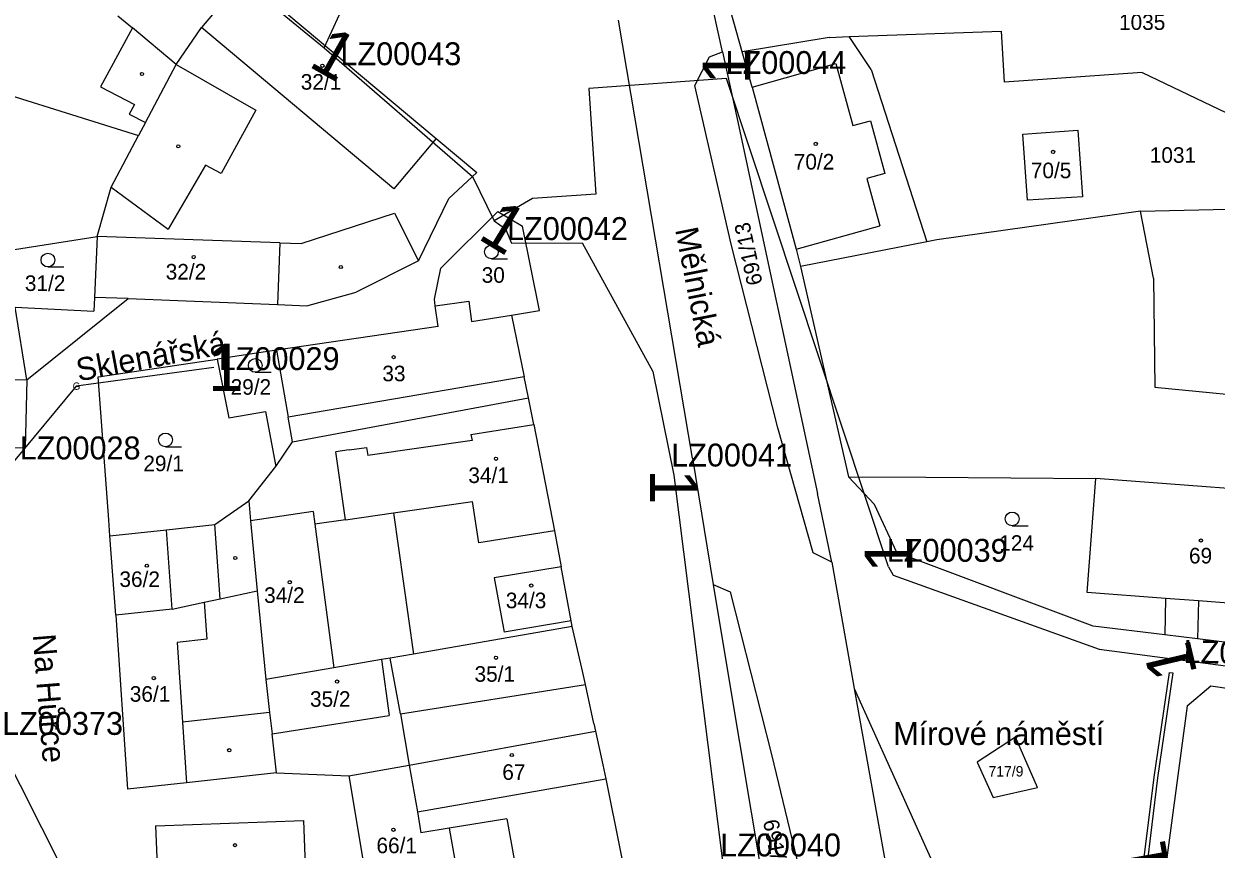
# Model space of a CAD drawing. Extents: x -738131 to -734179, y -1033447 to -1030078.
# Drawn here: x -736178.6 to -736048.4, y -1032166.9 to -1032076.8 of the extents above; entities that cross this region are included whole.
import ezdxf

# ---------------------------------------------------------------- set-up
doc = ezdxf.new("R2010")
doc.units = 0
for name, color, linetype in [('ftf_2010', 7, 'Continuous'), ('ftf_2050', 7, 'Continuous'), ('ftf_2080', 7, 'Continuous'), ('ftf_2140', 7, 'Continuous'), ('ftf_3010', 7, 'Continuous'), ('ftf_3010_ftf_3010_gtda_3015_gtda_3015_1', 7, 'Continuous'), ('ftf_3240', 7, 'Continuous'), ('ftf_nu', 7, 'Continuous'), ('Vrstva 1', 7, 'Continuous'), ('Vrstva 2', 7, 'Continuous'), ('Vrstva 3', 7, 'Continuous'), ('Vrstva 4', 7, 'Continuous'), ('Vrstva 5', 7, 'Continuous')]:
    doc.layers.add(name, color=color, linetype=linetype)

msp = doc.modelspace()

# ---------------------------------------------------------------- linework, layer by layer
at = {"layer": 'ftf_2010'}
for points in [[(-736173.87, -1032059), (-736155.52, -1032071.43), (-736145.76, -1032079.46)], [(-736145.76, -1032079.46), (-736129.57, -1032093.5), (-736127.21, -1032098.34)], [(-736101.83, -1032082.79), (-736116.85, -1032083.87), (-736116.08, -1032095.41), (-736123, -1032095.88), (-736127.21, -1032098.34)], [(-736084.14, -1032136.1), (-736101.83, -1032082.79)], [(-736127.21, -1032098.34), (-736125.97, -1032099.2), (-736125.31, -1032100.78), (-736117.57, -1032100.74), (-736109.87, -1032114.77), (-736107.59, -1032126.1)], [(-736107.59, -1032126.1), (-736102.25, -1032168.26)], [(-736084.14, -1032136.1), (-736083.63, -1032137.03), (-736061.14, -1032145.09), (-736042.04, -1032147.61), (-736033.38, -1032147.59)], [(-736053.07, -1032147.7), (-736054.74, -1032159.15), (-736056, -1032169.35)]]:
    msp.add_lwpolyline(points, dxfattribs=at)
at = {"layer": 'ftf_2050'}
for points in [[(-736157.8, -1032114.33), (-736172.83, -1032116.38), (-736179.72, -1032124.69)], [(-736181.33, -1032155.34), (-736169.66, -1032178.44)]]:
    msp.add_lwpolyline(points, dxfattribs=at)
at = {"layer": 'ftf_2080'}
msp.add_lwpolyline([(-736145.76, -1032079.46), (-736141.56, -1032070.31)], dxfattribs=at)
at = {"layer": 'ftf_2140'}
msp.add_lwpolyline([(-736059.51, -1032203.25), (-736059.59, -1032203.64), (-736061.73, -1032203.22), (-736058.65, -1032185.85), (-736058.24, -1032185.72), (-736058.61, -1032185.64), (-736057.52, -1032177.44), (-736056.42, -1032169.43), (-736056, -1032169.35), (-736056.4, -1032169.3), (-736055.13, -1032159.09), (-736053.46, -1032147.65), (-736053.07, -1032147.7)], dxfattribs=at)
at = {"layer": 'Vrstva 1'}
for points in [[(-736154.53, -1032071.72), (-736159.15, -1032077.23)], [(-736154.53, -1032071.72), (-736133.52, -1032089.34)], [(-736102.26, -1032079.87), (-736103.75, -1032073.06)], [(-736100.1, -1032079.88), (-736101.68, -1032074.32)], [(-736105.53, -1032124.24), (-736113.62, -1032076.42)], [(-736161.91, -1032081.28), (-736159.15, -1032077.23)], [(-736088.44, -1032078.22), (-736071.79, -1032077.63)], [(-736071.46, -1032083.19), (-736071.79, -1032077.63)], [(-736090.61, -1032078.3), (-736100.1, -1032079.88)], [(-736090.61, -1032078.3), (-736088.44, -1032078.22)], [(-736086.02, -1032081.8), (-736088.44, -1032078.22)], [(-736103.68, -1032080.44), (-736102.26, -1032079.87)], [(-736102.26, -1032079.87), (-736100.66, -1032087.2)], [(-736099.01, -1032083.73), (-736100.1, -1032079.88)], [(-736165.28, -1032087.61), (-736161.91, -1032081.28)], [(-736105.27, -1032083.57), (-736103.68, -1032080.44)], [(-736187.43, -1032082.32), (-736166.03, -1032089.02)], [(-736086.02, -1032081.8), (-736079.93, -1032100.61)], [(-736056.43, -1032082.12), (-736071.46, -1032083.19)], [(-736056.43, -1032082.12), (-736039.76, -1032090.12)], [(-736101.33, -1032100.88), (-736105.27, -1032083.57)], [(-736099.01, -1032083.73), (-736094.2, -1032101.44)], [(-736165.28, -1032087.61), (-736166.03, -1032089.02)], [(-736100.66, -1032087.2), (-736091.9, -1032128.1)], [(-736169.02, -1032094.66), (-736166.03, -1032089.02)], [(-736133.52, -1032089.34), (-736129.08, -1032093.07)], [(-736069.48, -1032088.87), (-736063.45, -1032088.43)], [(-736068.97, -1032096.09), (-736069.48, -1032088.87)], [(-736063.45, -1032088.43), (-736062.95, -1032095.7)], [(-736129.08, -1032093.07), (-736132.15, -1032095.9)], [(-736170.56, -1032100.05), (-736169.02, -1032094.66)], [(-736135.47, -1032102.71), (-736132.15, -1032095.9)], [(-736062.95, -1032095.7), (-736068.97, -1032096.09)], [(-736056.61, -1032097.28), (-736039.13, -1032096.86)], [(-736133.01, -1032103.51), (-736126.81, -1032097.31)], [(-736126.81, -1032097.31), (-736124.12, -1032098.92)], [(-736056.61, -1032097.28), (-736078.84, -1032100.39)], [(-736055.2, -1032104.58), (-736056.61, -1032097.28)], [(-736122.26, -1032108.13), (-736124.12, -1032098.92)], [(-736181.49, -1032101.76), (-736170.56, -1032100.05)], [(-736170.56, -1032100.05), (-736170.85, -1032106.69)], [(-736150.62, -1032100.73), (-736170.56, -1032100.05)], [(-736150.62, -1032100.73), (-736150.85, -1032107.48)], [(-736096.21, -1032120.92), (-736101.33, -1032100.88)], [(-736079.93, -1032100.61), (-736093.76, -1032103.33)], [(-736078.84, -1032100.39), (-736079.93, -1032100.61)], [(-736094.2, -1032101.44), (-736093.76, -1032103.33)], [(-736135.47, -1032102.71), (-736142.26, -1032106.12)], [(-736133.73, -1032106.9), (-736133.01, -1032103.51)], [(-736093.76, -1032103.33), (-736088.49, -1032126.28)], [(-736055.2, -1032104.58), (-736055.04, -1032116.5)], [(-736147.66, -1032107.6), (-736142.26, -1032106.12)], [(-736178.24, -1032115.68), (-736167.17, -1032106.83)], [(-736170.85, -1032106.69), (-736170.91, -1032108.19)], [(-736167.17, -1032106.83), (-736150.85, -1032107.48)], [(-736150.85, -1032107.48), (-736147.66, -1032107.6)], [(-736133.63, -1032107.61), (-736133.73, -1032106.9)], [(-736133.63, -1032107.61), (-736129.97, -1032107.1)], [(-736133.32, -1032109.86), (-736133.63, -1032107.61)], [(-736129.97, -1032107.1), (-736129.66, -1032109.32)], [(-736178.24, -1032115.68), (-736179.52, -1032107.77)], [(-736179.52, -1032107.77), (-736170.91, -1032108.19)], [(-736129.66, -1032109.32), (-736125.32, -1032108.62)], [(-736125.32, -1032108.62), (-736122.26, -1032108.13)], [(-736125.32, -1032108.62), (-736123.92, -1032115.35)], [(-736133.32, -1032109.86), (-736150.98, -1032112.47)], [(-736150.98, -1032112.47), (-736157.46, -1032113.43)], [(-736150.98, -1032112.47), (-736149.68, -1032119.76)], [(-736170.43, -1032115.35), (-736157.46, -1032113.43)], [(-736157.46, -1032113.43), (-736156.18, -1032119.86)], [(-736169.29, -1032130.98), (-736170.43, -1032115.35)], [(-736123.46, -1032117.67), (-736123.92, -1032115.35)], [(-736191.64, -1032115.51), (-736178.24, -1032115.68)], [(-736178.24, -1032115.68), (-736178.43, -1032123.14)], [(-736055.04, -1032116.5), (-736026.73, -1032119.25)], [(-736149.21, -1032122.45), (-736123.46, -1032117.67)], [(-736122.88, -1032120.58), (-736123.46, -1032117.67)], [(-736156.18, -1032119.86), (-736152.18, -1032119.16)], [(-736152.18, -1032119.16), (-736151.03, -1032125.16)], [(-736149.21, -1032122.45), (-736149.68, -1032119.76)], [(-736122.88, -1032120.58), (-736120.62, -1032132.18)], [(-736092.35, -1032134.6), (-736096.21, -1032120.92)], [(-736178.43, -1032123.14), (-736180.63, -1032123.11)], [(-736151.03, -1032125.16), (-736149.21, -1032122.45)], [(-736105.53, -1032124.24), (-736103.27, -1032138.05)], [(-736154, -1032128.89), (-736151.03, -1032125.16)], [(-736085.67, -1032129.29), (-736088.49, -1032126.28)], [(-736088.49, -1032126.28), (-736080.05, -1032126.33)], [(-736080.05, -1032126.33), (-736061.48, -1032126.45)], [(-736062.43, -1032138.91), (-736061.48, -1032126.45)], [(-736090.33, -1032135.6), (-736091.9, -1032128.1)], [(-736157.72, -1032131.5), (-736154, -1032128.89)], [(-736154, -1032128.89), (-736153.79, -1032131.08)], [(-736138.2, -1032130.23), (-736129.55, -1032128.99)], [(-736128.87, -1032133.49), (-736129.55, -1032128.99)], [(-736083.23, -1032134.54), (-736085.67, -1032129.29)], [(-736169.16, -1032132.74), (-736169.29, -1032130.98)], [(-736146.95, -1032130.06), (-736153.79, -1032131.08)], [(-736153.79, -1032131.08), (-736153.07, -1032138.72)], [(-736146.95, -1032130.06), (-736146.77, -1032131.45)], [(-736143.45, -1032130.98), (-736146.77, -1032131.45)], [(-736143.45, -1032130.98), (-736138.2, -1032130.23)], [(-736138.2, -1032130.23), (-736136.02, -1032145.63)], [(-736169.16, -1032132.74), (-736162.98, -1032132.07)], [(-736162.98, -1032132.07), (-736157.72, -1032131.5)], [(-736120.62, -1032132.18), (-736128.87, -1032133.49)], [(-736120.62, -1032132.18), (-736119.89, -1032136.11)], [(-736168.53, -1032141.4), (-736169.16, -1032132.74)], [(-736090.33, -1032135.6), (-736092.35, -1032134.6)], [(-736061.77, -1032142.59), (-736083.23, -1032134.54)], [(-736118.8, -1032142.01), (-736119.89, -1032136.11)], [(-736090.33, -1032135.6), (-736087.87, -1032149.39)], [(-736157.13, -1032139.6), (-736153.07, -1032138.72)], [(-736153.07, -1032138.72), (-736152.14, -1032148.42)], [(-736103.27, -1032138.05), (-736101.43, -1032138.83)], [(-736103.27, -1032138.05), (-736101.65, -1032147.92)], [(-736101.43, -1032138.83), (-736096.91, -1032156.59)], [(-736053.87, -1032139.56), (-736062.43, -1032138.91)], [(-736162.35, -1032140.73), (-736158.86, -1032139.97)], [(-736158.86, -1032139.97), (-736157.13, -1032139.6)], [(-736053.87, -1032139.56), (-736053.96, -1032143.54)], [(-736050.28, -1032139.83), (-736050.38, -1032143.98)], [(-736041.89, -1032140.47), (-736050.28, -1032139.83)], [(-736162.35, -1032140.73), (-736168.53, -1032141.4)], [(-736168.53, -1032141.4), (-736167.25, -1032160.38)], [(-736118.69, -1032142.63), (-736136.02, -1032145.63)], [(-736118.69, -1032142.63), (-736118.8, -1032142.01)], [(-736117.51, -1032147.64), (-736118.69, -1032142.63)], [(-736053.96, -1032143.54), (-736061.77, -1032142.59)], [(-736050.38, -1032143.98), (-736053.96, -1032143.54)], [(-736041.81, -1032145.03), (-736050.38, -1032143.98)], [(-736139.51, -1032146.24), (-736144.71, -1032147.13)], [(-736138.55, -1032146.07), (-736139.51, -1032146.24)], [(-736136.02, -1032145.63), (-736138.55, -1032146.07)], [(-736137.44, -1032152.17), (-736138.55, -1032146.07)], [(-736144.71, -1032147.13), (-736152.14, -1032148.42)], [(-736117.23, -1032148.95), (-736117.51, -1032147.64)], [(-736101.65, -1032147.92), (-736095.37, -1032185.27)], [(-736152.14, -1032148.42), (-736151.72, -1032152.03)], [(-736116.32, -1032153.2), (-736117.23, -1032148.95)], [(-736051.51, -1032151.29), (-736048.93, -1032149.09)], [(-736048.93, -1032149.09), (-736011.61, -1032154.54)], [(-736087.87, -1032149.39), (-736081.88, -1032182.97)], [(-736087.87, -1032149.39), (-736067.88, -1032193.8)], [(-736051.51, -1032151.29), (-736056.56, -1032189.07)], [(-736151.72, -1032152.03), (-736151.46, -1032154.34)], [(-736137.44, -1032152.17), (-736136.47, -1032157.75)], [(-736116.32, -1032153.2), (-736116.13, -1032154.05)], [(-736150.96, -1032158.62), (-736151.46, -1032154.34)], [(-736136.47, -1032157.75), (-736116.13, -1032154.05)], [(-736116.13, -1032154.05), (-736115.32, -1032157.74)], [(-736070.28, -1032154.72), (-736074.45, -1032157.43)], [(-736067.86, -1032160.21), (-736070.28, -1032154.72)], [(-736096.91, -1032156.59), (-736093.17, -1032172.14)], [(-736143.06, -1032158.95), (-736136.47, -1032157.75)], [(-736136.47, -1032157.75), (-736135.58, -1032162.86)], [(-736115.32, -1032157.74), (-736115.01, -1032159.26)], [(-736074.45, -1032157.43), (-736072.69, -1032161.3)], [(-736160.78, -1032159.68), (-736167.25, -1032160.38)], [(-736150.96, -1032158.62), (-736160.78, -1032159.68)], [(-736150.96, -1032158.62), (-736143.06, -1032158.95)], [(-736143.06, -1032158.95), (-736140.37, -1032175.05)], [(-736115.01, -1032159.26), (-736111.82, -1032175.01)], [(-736072.69, -1032161.3), (-736067.86, -1032160.21)], [(-736135.58, -1032162.86), (-736135.19, -1032165.15)], [(-736125.82, -1032163.63), (-736132.11, -1032164.65)], [(-736125.82, -1032163.63), (-736123.41, -1032176.95)], [(-736164.18, -1032164.4), (-736148.02, -1032163.8)], [(-736164.18, -1032164.4), (-736163.84, -1032172.23)], [(-736148.02, -1032163.8), (-736147.73, -1032171.63)], [(-736132.11, -1032164.65), (-736135.19, -1032165.15)]]:
    msp.add_lwpolyline(points, dxfattribs=at)
at = {"layer": 'Vrstva 3'}
for p, q in [((-736175.93, -1032103.36), (-736174.18, -1032103.36)), ((-736127.5, -1032102.48), (-736125.75, -1032102.48)), ((-736153.29, -1032114.87), (-736151.54, -1032114.87)), ((-736163.09, -1032123.01), (-736161.34, -1032123.01)), ((-736070.63, -1032131.63), (-736068.88, -1032131.63))]:
    msp.add_line(p, q, dxfattribs=at)
for centre in [(-736127.5, -1032101.73), (-736175.93, -1032102.61), (-736153.29, -1032114.12), (-736163.09, -1032122.26), (-736070.63, -1032130.88)]:
    msp.add_circle(centre, 0.75, dxfattribs=at)
at = {"layer": 'Vrstva 4'}
for points in [[(-736168.29, -1032075.94), (-736166.69, -1032077.25)], [(-736166.69, -1032077.25), (-736170.2, -1032083.7)], [(-736161.91, -1032081.28), (-736166.69, -1032077.25)], [(-736138.14, -1032094.85), (-736159.15, -1032077.23)], [(-736161.91, -1032081.28), (-736153.23, -1032086.24)], [(-736099.01, -1032083.73), (-736089.87, -1032081.15)], [(-736089.87, -1032081.15), (-736088.04, -1032087.92)], [(-736170.2, -1032083.7), (-736166.47, -1032085.63)], [(-736166.47, -1032085.63), (-736167.05, -1032086.67)], [(-736167.05, -1032086.67), (-736165.28, -1032087.61)], [(-736153.23, -1032086.24), (-736157, -1032093.18)], [(-736088.04, -1032087.92), (-736086.11, -1032087.4)], [(-736086.11, -1032087.4), (-736084.55, -1032093.18)], [(-736133.52, -1032089.34), (-736138.14, -1032094.85)], [(-736158.71, -1032092.24), (-736162.8, -1032099.23)], [(-736157, -1032093.18), (-736158.71, -1032092.24)], [(-736084.55, -1032093.18), (-736086.49, -1032093.7)], [(-736086.49, -1032093.7), (-736085.09, -1032098.88)], [(-736169.02, -1032094.66), (-736162.8, -1032099.23)], [(-736148.27, -1032100.81), (-736138.1, -1032097.49)], [(-736138.1, -1032097.49), (-736135.47, -1032102.71)], [(-736094.2, -1032101.44), (-736085.09, -1032098.88)], [(-736150.62, -1032100.73), (-736148.27, -1032100.81)], [(-736167.17, -1032106.83), (-736170.85, -1032106.69)], [(-736123.92, -1032115.35), (-736149.68, -1032119.76)], [(-736129.73, -1032121.66), (-736122.88, -1032120.58)], [(-736129.73, -1032121.66), (-736129.61, -1032122.32)], [(-736143.05, -1032123.34), (-736141.14, -1032123.07)], [(-736141.14, -1032123.07), (-736141, -1032123.95)], [(-736129.61, -1032122.32), (-736141, -1032123.95)], [(-736143.05, -1032123.34), (-736144.5, -1032123.55)], [(-736143.45, -1032130.98), (-736144.5, -1032123.55)], [(-736035.46, -1032128.43), (-736061.48, -1032126.45)], [(-736162.35, -1032140.73), (-736162.98, -1032132.07)], [(-736157.13, -1032139.6), (-736157.72, -1032131.5)], [(-736146.77, -1032131.45), (-736144.71, -1032147.13)], [(-736119.89, -1032136.11), (-736127.2, -1032137.31)], [(-736127.2, -1032137.31), (-736126.1, -1032143.26)], [(-736158.86, -1032139.97), (-736158.58, -1032144.02)], [(-736050.28, -1032139.83), (-736053.87, -1032139.56)], [(-736118.8, -1032142.01), (-736126.1, -1032143.26)], [(-736158.58, -1032144.02), (-736161.81, -1032144.38)], [(-736161.81, -1032144.38), (-736161.23, -1032153.06)], [(-736139.51, -1032146.24), (-736138.68, -1032152.36)], [(-736137.44, -1032152.17), (-736117.23, -1032148.95)], [(-736151.72, -1032152.03), (-736161.23, -1032153.06)], [(-736161.23, -1032153.06), (-736160.78, -1032159.68)], [(-736151.46, -1032154.34), (-736138.68, -1032152.36)], [(-736135.58, -1032162.86), (-736115.01, -1032159.26)], [(-736132.11, -1032164.65), (-736131.48, -1032168.13)]]:
    msp.add_lwpolyline(points, dxfattribs=at)
at = {"layer": 'Vrstva 5'}
for centre in [(-736145.95, -1032081.4), (-736165.66, -1032082.3), (-736161.69, -1032090.2), (-736092.08, -1032089.93), (-736066.16, -1032090.81), (-736160.01, -1032102.29), (-736143.94, -1032103.38), (-736138.18, -1032113.22), (-736127, -1032124.31), (-736050.02, -1032133.24), (-736155.47, -1032135.15), (-736165.13, -1032135.99), (-736149.52, -1032137.79), (-736123.15, -1032138.16), (-736127, -1032146.04), (-736164.37, -1032148.26), (-736144.35, -1032148.64), (-736156.13, -1032156.14), (-736125.27, -1032156.66), (-736138.2, -1032164.82), (-736155.5, -1032166.5)]:
    msp.add_circle(centre, 0.175, dxfattribs=at)

# ---------------------------------------------------------------- texts
at = {"layer": 'ftf_3010'}
for rotation, p in [(330.5165, (-736147.6, -1032081.4)), (90, (-736099.23, -1032083.44)), (328.7171, (-736129.12, -1032100.22)), (270, (-736110.19, -1032125.45)), (90, (-736081.54, -1032136.75)), (103.2874, (-736050.39, -1032147.74)), (99.9677, (-736053.33, -1032169.53))]:
    msp.add_text('1', height=5.2, rotation=rotation, dxfattribs=at).set_placement(p)
msp.add_text('1', height=5.2, dxfattribs=at).set_placement((-736158.45, -1032116.93))
at = {"layer": 'ftf_3010_ftf_3010_gtda_3015_gtda_3015_1'}
for s, p in [('LZ00043', (-736143.99, -1032081.34)), ('LZ00029', (-736157.28, -1032114.63))]:
    msp.add_text(s, height=2.5, dxfattribs=at).set_placement(p)
for s, rotation, p in [('LZ00044', 0, (-736101.93, -1032082.3)), ('LZ00042', 0, (-736125.79, -1032100.43)), ('LZ00028', 0, (-736179.01, -1032124.38)), ('LZ00041', 0, (-736107.87, -1032125.16)), ('LZ00039', 0, (-736084.32, -1032135.56)), ('LZ00331', 358.7101, (-736051.93, -1032146.59)), ('LZ00373', 0, (-736180.93, -1032154.46)), ('LZ00040', 0, (-736102.52, -1032167.73))]:
    msp.add_text(s, height=2.5, rotation=rotation, dxfattribs=at).set_placement(p)
at = {"layer": 'ftf_3240'}
msp.add_text('G', height=0.8, dxfattribs=at).set_placement((-736173.23, -1032116.78))
at = {"layer": 'ftf_nu'}
for s, rotation, p in [('Mělnická', 281.1659, (-736107.45, -1032099.28)), ('Sklenářská', 10.5891, (-736172.59, -1032115.87)), ('Na Hůrce', 274.5703, (-736177.6, -1032143.53))]:
    msp.add_text(s, height=2.5, rotation=rotation, dxfattribs=at).set_placement(p)
msp.add_text('Mírové náměstí', height=2.5, dxfattribs=at).set_placement((-736083.62, -1032155.57))
at = {"layer": 'Vrstva 2'}
for s, height, p in [('1035', 1.7, (-736058.96, -1032077.49)), ('32/1', 1.7, (-736148.32, -1032084.01)), ('1031', 1.7, (-736055.6, -1032092)), ('70/2', 1.7, (-736094.48, -1032092.73)), ('70/5', 1.7, (-736068.59, -1032093.68)), ('32/2', 1.7, (-736163.07, -1032104.74)), ('30', 1.7, (-736128.56, -1032105.1)), ('31/2', 1.7, (-736178.45, -1032105.99)), ('33', 1.7, (-736139.41, -1032115.85)), ('29/2', 1.7, (-736155.98, -1032117.32)), ('29/1', 1.7, (-736165.51, -1032125.67)), ('34/1', 1.7, (-736130.02, -1032126.96)), ('124', 1.7, (-736072.04, -1032134.36)), ('69', 1.7, (-736051.32, -1032135.74)), ('36/2', 1.7, (-736168.12, -1032138.31)), ('34/2', 1.7, (-736152.32, -1032140.05)), ('34/3', 1.7, (-736125.93, -1032140.63)), ('35/1', 1.7, (-736129.34, -1032148.66)), ('36/1', 1.7, (-736166.99, -1032150.84)), ('35/2', 1.7, (-736147.31, -1032151.39)), ('67', 1.7, (-736126.31, -1032159.37)), ('717/9', 1.14, (-736073.21, -1032159.01)), ('66/1', 1.7, (-736140.05, -1032167.38))]:
    msp.add_text(s, height=height, dxfattribs=at).set_placement(p)
for s, rotation, p in [('691/13', 102.181, (-736097.87, -1032105.17)), ('691/12', 281.3099, (-736097.85, -1032163.87))]:
    msp.add_text(s, height=1.7, rotation=rotation, dxfattribs=at).set_placement(p)

doc.saveas('drawing.dxf')
